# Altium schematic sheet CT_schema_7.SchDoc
size 253 x 245 mm
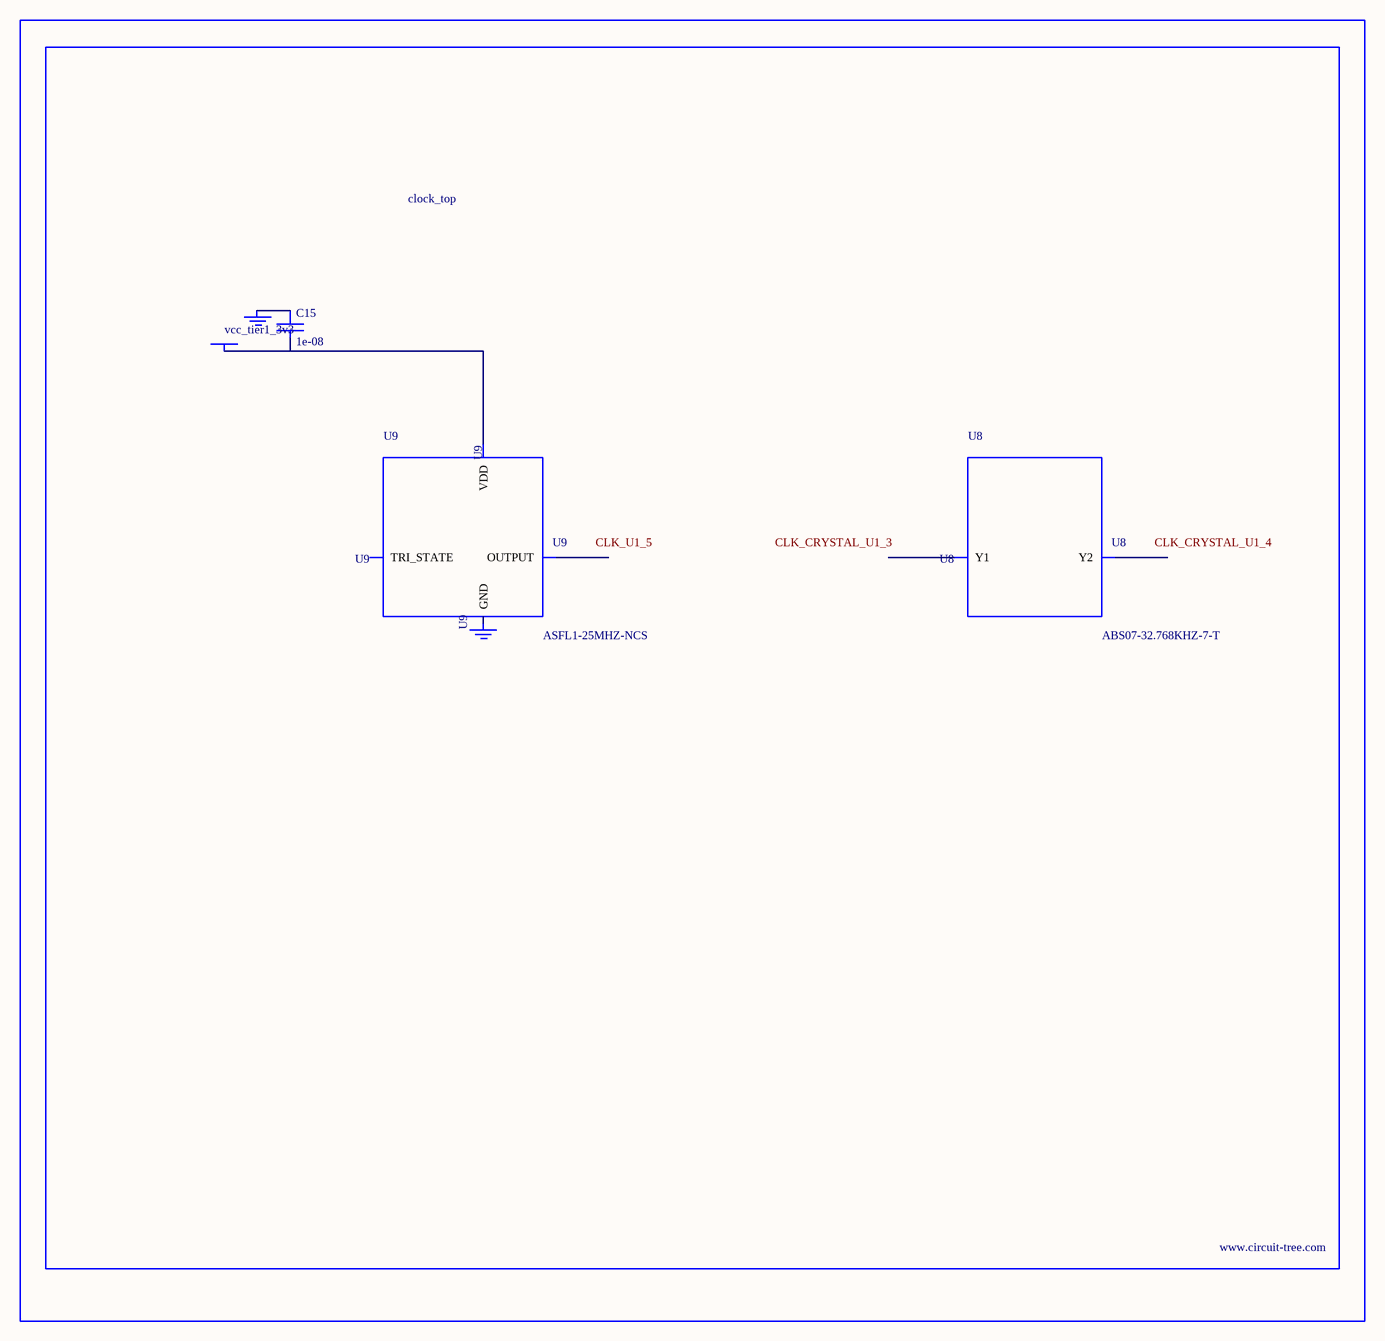
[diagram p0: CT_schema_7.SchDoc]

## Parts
BORDER6  (no value)
C15  1e-08  [C0402]
GND_INSTANCE_6_0  (no value)
GND_INSTANCE_6_1  (no value)
POWER_INSTANCE_6_0  vcc_tier1_3v3
U8  ABS07-32.768KHZ-7-T  [ABS07-32.768KHZ-7-T]
U9  ASFL1-25MHZ-NCS  [ASFL1]

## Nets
NetC15_1: C15.1 GND_INSTANCE_6_0.0(GND)
NetC15_2: C15.2 POWER_INSTANCE_6_0.0(PWR) U9.4(VDD)

Not connected (* = marked no-connect by the designer): GND_INSTANCE_6_1 0(GND); U8 1(Y1) 2(Y2); U9 1(TRI_STATE) 2(GND) 3(OUTPUT)

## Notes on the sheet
- Labels drawn without touching a wire or pin: CLK_CRYSTAL_U1_3, CLK_CRYSTAL_U1_4, CLK_U1_5

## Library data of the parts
BORDER6 = BORDER_PAGE6
C15 = C0402C103K3RAC
GND_INSTANCE_6_0 GND_INSTANCE_6_1 = GND
POWER_INSTANCE_6_0 = PWR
